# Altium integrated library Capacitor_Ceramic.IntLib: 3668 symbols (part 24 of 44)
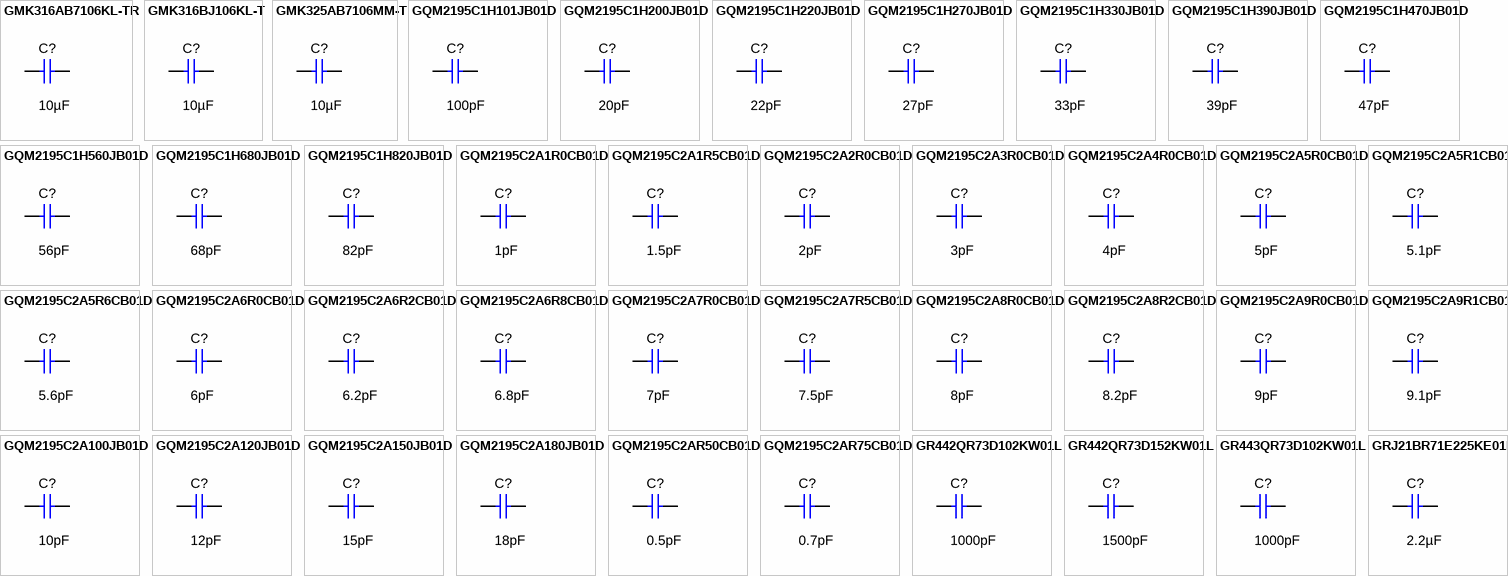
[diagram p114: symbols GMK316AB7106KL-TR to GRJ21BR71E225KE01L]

## GQM2195C2A5R1CB01D
designator C?  ValueDisplayed: 5.1pF  (hidden comment: GQM2195C2A5R1CB01D)
CAP, CERM, 5.1 pF, 100 V,+/- 5%, C0G/NP0, 0805; Manufacturer: MuRata; Polarized: N; CompType: Capacitor; Value: 5.1pF; U/M: EA; Cap_F: 0.0000000000051; Tolerance_%: 5; VDC_V: 100; Value2: 100V; TaMin_C: -55; TaMax_C: 125; Cap_Case: 0805; SizeArea_mm2: 2.5; SizeAreaWB_mm2: 6.75; SizeX_mm: 2; SizeY_mm: 1.25; SizeZ_mm: 1.45; AEC Category: Q200
signal-integrity model Cap
simulation model Cap
footprint 0805_HV
footprint 0805_HV1
footprint 0805
footprint 0805M
footprint 0805L
pins: 1, 2

## GQM2195C2A5R6CB01D
designator C?  ValueDisplayed: 5.6pF  (hidden comment: GQM2195C2A5R6CB01D)
CAP, CERM, 5.6 pF, 100 V,+/- 5%, C0G/NP0, 0805; Manufacturer: MuRata; Polarized: N; CompType: Capacitor; Value: 5.6pF; U/M: EA; Cap_F: 0.0000000000056; Tolerance_%: 5; VDC_V: 100; Value2: 100V; TaMin_C: -55; TaMax_C: 125; Cap_Case: 0805; SizeArea_mm2: 2.5; SizeAreaWB_mm2: 6.75; SizeX_mm: 2; SizeY_mm: 1.25; SizeZ_mm: 1.45; AEC Category: Q200
signal-integrity model Cap
simulation model Cap
footprint 0805_HV
footprint 0805_HV1
footprint 0805
footprint 0805M
footprint 0805L
pins: 1, 2

## GQM2195C2A6R0CB01D
designator C?  ValueDisplayed: 6pF  (hidden comment: GQM2195C2A6R0CB01D)
CAP, CERM, 6 pF, 100 V,+/- 5%, C0G/NP0, 0805; Manufacturer: MuRata; Polarized: N; CompType: Capacitor; Value: 6pF; U/M: EA; Cap_F: 0.000000000006; Tolerance_%: 5; VDC_V: 100; Value2: 100V; TaMin_C: -55; TaMax_C: 125; Cap_Case: 0805; SizeArea_mm2: 2.5; SizeAreaWB_mm2: 6.75; SizeX_mm: 2; SizeY_mm: 1.25; SizeZ_mm: 1.45; AEC Category: Q200
signal-integrity model Cap
simulation model Cap
footprint 0805_HV
footprint 0805_HV1
footprint 0805
footprint 0805M
footprint 0805L
pins: 1, 2

## GQM2195C2A6R2CB01D
designator C?  ValueDisplayed: 6.2pF  (hidden comment: GQM2195C2A6R2CB01D)
CAP, CERM, 6.2 pF, 100 V,+/- 5%, C0G/NP0, 0805; Manufacturer: MuRata; Polarized: N; CompType: Capacitor; Value: 6.2pF; U/M: EA; Cap_F: 0.0000000000062; Tolerance_%: 5; VDC_V: 100; Value2: 100V; TaMin_C: -55; TaMax_C: 125; Cap_Case: 0805; SizeArea_mm2: 2.5; SizeAreaWB_mm2: 6.75; SizeX_mm: 2; SizeY_mm: 1.25; SizeZ_mm: 1.45; AEC Category: Q200
signal-integrity model Cap
simulation model Cap
footprint 0805_HV
footprint 0805_HV1
footprint 0805
footprint 0805M
footprint 0805L
pins: 1, 2

## GQM2195C2A6R8CB01D
designator C?  ValueDisplayed: 6.8pF  (hidden comment: GQM2195C2A6R8CB01D)
CAP, CERM, 6.8 pF, 100 V,+/- 5%, C0G/NP0, 0805; Manufacturer: MuRata; Polarized: N; CompType: Capacitor; Value: 6.8pF; U/M: EA; Cap_F: 0.0000000000068; Tolerance_%: 5; VDC_V: 100; Value2: 100V; TaMin_C: -55; TaMax_C: 125; Cap_Case: 0805; SizeArea_mm2: 2.5; SizeAreaWB_mm2: 6.75; SizeX_mm: 2; SizeY_mm: 1.25; SizeZ_mm: 1.45; AEC Category: Q200
signal-integrity model Cap
simulation model Cap
footprint 0805_HV
footprint 0805_HV1
footprint 0805
footprint 0805M
footprint 0805L
pins: 1, 2

## GQM2195C2A7R0CB01D
designator C?  ValueDisplayed: 7pF  (hidden comment: GQM2195C2A7R0CB01D)
CAP, CERM, 7 pF, 100 V,+/- 5%, C0G/NP0, 0805; Manufacturer: MuRata; Polarized: N; CompType: Capacitor; Value: 7pF; U/M: EA; Cap_F: 0.000000000007; Tolerance_%: 5; VDC_V: 100; Value2: 100V; TaMin_C: -55; TaMax_C: 125; Cap_Case: 0805; SizeArea_mm2: 2.5; SizeAreaWB_mm2: 6.75; SizeX_mm: 2; SizeY_mm: 1.25; SizeZ_mm: 1.45; AEC Category: Q200
signal-integrity model Cap
simulation model Cap
footprint 0805_HV
footprint 0805_HV1
footprint 0805
footprint 0805M
footprint 0805L
pins: 1, 2

## GQM2195C2A7R5CB01D
designator C?  ValueDisplayed: 7.5pF  (hidden comment: GQM2195C2A7R5CB01D)
CAP, CERM, 7.5 pF, 100 V,+/- 5%, C0G/NP0, 0805; Manufacturer: MuRata; Polarized: N; CompType: Capacitor; Value: 7.5pF; U/M: EA; Cap_F: 0.0000000000075; Tolerance_%: 5; VDC_V: 100; Value2: 100V; TaMin_C: -55; TaMax_C: 125; Cap_Case: 0805; SizeArea_mm2: 2.5; SizeAreaWB_mm2: 6.75; SizeX_mm: 2; SizeY_mm: 1.25; SizeZ_mm: 1.45; AEC Category: Q200
signal-integrity model Cap
simulation model Cap
footprint 0805_HV
footprint 0805_HV1
footprint 0805
footprint 0805M
footprint 0805L
pins: 1, 2

## GQM2195C2A8R0CB01D
designator C?  ValueDisplayed: 8pF  (hidden comment: GQM2195C2A8R0CB01D)
CAP, CERM, 8 pF, 100 V,+/- 5%, C0G/NP0, 0805; Manufacturer: MuRata; Polarized: N; CompType: Capacitor; Value: 8pF; U/M: EA; Cap_F: 0.000000000008; Tolerance_%: 5; VDC_V: 100; Value2: 100V; TaMin_C: -55; TaMax_C: 125; Cap_Case: 0805; SizeArea_mm2: 2.5; SizeAreaWB_mm2: 6.75; SizeX_mm: 2; SizeY_mm: 1.25; SizeZ_mm: 1.45; AEC Category: Q200
signal-integrity model Cap
simulation model Cap
footprint 0805_HV
footprint 0805_HV1
footprint 0805
footprint 0805M
footprint 0805L
pins: 1, 2

## GQM2195C2A8R2CB01D
designator C?  ValueDisplayed: 8.2pF  (hidden comment: GQM2195C2A8R2CB01D)
CAP, CERM, 8.2 pF, 100 V,+/- 5%, C0G/NP0, 0805; Manufacturer: MuRata; Polarized: N; CompType: Capacitor; Value: 8.2pF; U/M: EA; Cap_F: 0.0000000000082; Tolerance_%: 5; VDC_V: 100; Value2: 100V; TaMin_C: -55; TaMax_C: 125; Cap_Case: 0805; SizeArea_mm2: 2.5; SizeAreaWB_mm2: 6.75; SizeX_mm: 2; SizeY_mm: 1.25; SizeZ_mm: 1.45; AEC Category: Q200
signal-integrity model Cap
simulation model Cap
footprint 0805_HV
footprint 0805_HV1
footprint 0805
footprint 0805M
footprint 0805L
pins: 1, 2

## GQM2195C2A9R0CB01D
designator C?  ValueDisplayed: 9pF  (hidden comment: GQM2195C2A9R0CB01D)
CAP, CERM, 9 pF, 100 V,+/- 5%, C0G/NP0, 0805; Manufacturer: MuRata; Polarized: N; CompType: Capacitor; Value: 9pF; U/M: EA; Cap_F: 0.000000000009; Tolerance_%: 5; VDC_V: 100; Value2: 100V; TaMin_C: -55; TaMax_C: 125; Cap_Case: 0805; SizeArea_mm2: 2.5; SizeAreaWB_mm2: 6.75; SizeX_mm: 2; SizeY_mm: 1.25; SizeZ_mm: 1.45; AEC Category: Q200
signal-integrity model Cap
simulation model Cap
footprint 0805_HV
footprint 0805_HV1
footprint 0805
footprint 0805M
footprint 0805L
pins: 1, 2

## GQM2195C2A9R1CB01D
designator C?  ValueDisplayed: 9.1pF  (hidden comment: GQM2195C2A9R1CB01D)
CAP, CERM, 9.1 pF, 100 V,+/- 5%, C0G/NP0, 0805; Manufacturer: MuRata; Polarized: N; CompType: Capacitor; Value: 9.1pF; U/M: EA; Cap_F: 0.0000000000091; Tolerance_%: 5; VDC_V: 100; Value2: 100V; TaMin_C: -55; TaMax_C: 125; Cap_Case: 0805; SizeArea_mm2: 2.5; SizeAreaWB_mm2: 6.75; SizeX_mm: 2; SizeY_mm: 1.25; SizeZ_mm: 1.45; AEC Category: Q200
signal-integrity model Cap
simulation model Cap
footprint 0805_HV
footprint 0805_HV1
footprint 0805
footprint 0805M
footprint 0805L
pins: 1, 2

## GQM2195C2A100JB01D
designator C?  ValueDisplayed: 10pF  (hidden comment: GQM2195C2A100JB01D)
CAP, CERM, 10 pF, 100 V,+/- 5%, C0G/NP0, 0805; Manufacturer: MuRata; Polarized: N; CompType: Capacitor; Value: 10pF; U/M: EA; Cap_F: 0.00000000001; Tolerance_%: 5; VDC_V: 100; Value2: 100V; TaMin_C: -55; TaMax_C: 125; Cap_Case: 0805; SizeArea_mm2: 2.5; SizeAreaWB_mm2: 6.75; SizeX_mm: 2; SizeY_mm: 1.25; SizeZ_mm: 1.45; AEC Category: Q200
signal-integrity model Cap
simulation model Cap
footprint 0805_HV
footprint 0805_HV1
footprint 0805
footprint 0805M
footprint 0805L
pins: 1, 2

## GQM2195C2A120JB01D
designator C?  ValueDisplayed: 12pF  (hidden comment: GQM2195C2A120JB01D)
CAP, CERM, 12 pF, 100 V,+/- 5%, C0G/NP0, 0805; Manufacturer: MuRata; Polarized: N; CompType: Capacitor; Value: 12pF; U/M: EA; Cap_F: 0.000000000012; Tolerance_%: 5; VDC_V: 100; Value2: 100V; TaMin_C: -55; TaMax_C: 125; Cap_Case: 0805; SizeArea_mm2: 2.5; SizeAreaWB_mm2: 6.75; SizeX_mm: 2; SizeY_mm: 1.25; SizeZ_mm: 1.45; AEC Category: Q200
signal-integrity model Cap
simulation model Cap
footprint 0805_HV
footprint 0805_HV1
footprint 0805
footprint 0805M
footprint 0805L
pins: 1, 2

## GQM2195C2A150JB01D
designator C?  ValueDisplayed: 15pF  (hidden comment: GQM2195C2A150JB01D)
CAP, CERM, 15 pF, 100 V,+/- 5%, C0G/NP0, 0805; Manufacturer: MuRata; Polarized: N; CompType: Capacitor; Value: 15pF; U/M: EA; Cap_F: 0.000000000015; Tolerance_%: 5; VDC_V: 100; Value2: 100V; TaMin_C: -55; TaMax_C: 125; Cap_Case: 0805; SizeArea_mm2: 2.5; SizeAreaWB_mm2: 6.75; SizeX_mm: 2; SizeY_mm: 1.25; SizeZ_mm: 1.45; AEC Category: Q200
signal-integrity model Cap
simulation model Cap
footprint 0805_HV
footprint 0805_HV1
footprint 0805
footprint 0805M
footprint 0805L
pins: 1, 2

## GQM2195C2A180JB01D
designator C?  ValueDisplayed: 18pF  (hidden comment: GQM2195C2A180JB01D)
CAP, CERM, 18 pF, 100 V,+/- 5%, C0G/NP0, 0805; Manufacturer: MuRata; Polarized: N; CompType: Capacitor; Value: 18pF; U/M: EA; Cap_F: 0.000000000018; Tolerance_%: 5; VDC_V: 100; Value2: 100V; TaMin_C: -55; TaMax_C: 125; Cap_Case: 0805; SizeArea_mm2: 2.5; SizeAreaWB_mm2: 6.75; SizeX_mm: 2; SizeY_mm: 1.25; SizeZ_mm: 1.45; AEC Category: Q200
signal-integrity model Cap
simulation model Cap
footprint 0805_HV
footprint 0805_HV1
footprint 0805
footprint 0805M
footprint 0805L
pins: 1, 2

## GQM2195C2AR50CB01D
designator C?  ValueDisplayed: 0.5pF  (hidden comment: GQM2195C2AR50CB01D)
CAP, CERM, 0.5 pF, 100 V,+/- 5%, C0G/NP0, 0805; Manufacturer: MuRata; Polarized: N; CompType: Capacitor; Value: 0.5pF; U/M: EA; Cap_F: 0.0000000000005; Tolerance_%: 5; VDC_V: 100; Value2: 100V; TaMin_C: -55; TaMax_C: 125; Cap_Case: 0805; SizeArea_mm2: 2.5; SizeAreaWB_mm2: 6.75; SizeX_mm: 2; SizeY_mm: 1.25; SizeZ_mm: 1.45; AEC Category: Q200
signal-integrity model Cap
simulation model Cap
footprint 0805_HV
footprint 0805_HV1
footprint 0805
footprint 0805M
footprint 0805L
pins: 1, 2

## GQM2195C2AR75CB01D
designator C?  ValueDisplayed: 0.7pF  (hidden comment: GQM2195C2AR75CB01D)
CAP, CERM, 0.7 pF, 100 V,+/- 5%, C0G/NP0, 0805; Manufacturer: MuRata; Polarized: N; CompType: Capacitor; Value: 0.7pF; U/M: EA; Cap_F: 0.0000000000007; Tolerance_%: 5; VDC_V: 100; Value2: 100V; TaMin_C: -55; TaMax_C: 125; Cap_Case: 0805; SizeArea_mm2: 2.5; SizeAreaWB_mm2: 6.75; SizeX_mm: 2; SizeY_mm: 1.25; SizeZ_mm: 1.45; AEC Category: Q200
signal-integrity model Cap
simulation model Cap
footprint 0805_HV
footprint 0805_HV1
footprint 0805
footprint 0805M
footprint 0805L
pins: 1, 2

## GR442QR73D102KW01L
designator C?  ValueDisplayed: 1000pF  (hidden comment: GR442QR73D102KW01L)
CAP, CERM, 1000 pF, 2000 V,+/- 10%, X7R, 1808; Manufacturer: MuRata; Polarized: N; CompType: Capacitor; Value: 1000pF; U/M: EA; Cap_F: 0.000000001; Tolerance_%: 10; VDC_V: 2000; Value2: 2000V; TaMin_C: -55; TaMax_C: 125; Cap_Case: 1808; SizeArea_mm2: 9; SizeAreaWB_mm2: 16.5; SizeX_mm: 4.5; SizeY_mm: 2; SizeZ_mm: 2.03; AEC Category: Q200
signal-integrity model Cap
simulation model Cap
footprint 1808
footprint 1808_M
footprint 1808_L
pins: 1, 2

## GR442QR73D152KW01L
designator C?  ValueDisplayed: 1500pF  (hidden comment: GR442QR73D152KW01L)
CAP, CERM, 1500 pF, 2000 V,+/- 10%, X7R, 1808; Manufacturer: MuRata; Polarized: N; CompType: Capacitor; Value: 1500pF; U/M: EA; Cap_F: 0.0000000015; Tolerance_%: 10; VDC_V: 2000; Value2: 2000V; TaMin_C: -55; TaMax_C: 125; Cap_Case: 1808; SizeArea_mm2: 9; SizeAreaWB_mm2: 16.5; SizeX_mm: 4.5; SizeY_mm: 2; SizeZ_mm: 2.03; AEC Category: Q200; Green_Lifecycle: Not Set; Green_REACh: Incomplete
signal-integrity model Cap
simulation model Cap
footprint 1808
footprint 1808_M
footprint 1808_L
pins: 1, 2

## GR443QR73D102KW01L
designator C?  ValueDisplayed: 1000pF  (hidden comment: GR443QR73D102KW01L)
CAP, CERM, 1000 pF, 2000 V,+/- 10%, X7R, 1812; Manufacturer: MuRata; Polarized: N; CompType: Capacitor; Value: 1000pF; U/M: EA; Cap_F: 0.000000001; Tolerance_%: 10; VDC_V: 2000; Value2: 2000V; TaMin_C: -55; TaMax_C: 125; Cap_Case: 1812; SizeArea_mm2: 14.4; SizeAreaWB_mm2: 23.1; SizeX_mm: 4.5; SizeY_mm: 3.2; SizeZ_mm: 1.35; AEC Category: Q200
signal-integrity model Cap
simulation model Cap
footprint 1812
footprint 1812M
footprint 1812L
footprint 1812_HV
pins: 1, 2

## GRJ21BR71E225KE01L
designator C?  ValueDisplayed: 2.2µF  (hidden comment: GRJ21BR71E225KE01L)
CAP, CERM, 2.2 µF, 25 V,+/- 10%, X7R, 0805; Manufacturer: MuRata; Polarized: N; CompType: Capacitor; Value: 2.2uF; U/M: EA; Cap_F: 0.0000022; Tolerance_%: 10; VDC_V: 25; Value2: 25V; TaMin_C: -55; TaMax_C: 125; Cap_Case: 0805; SizeArea_mm2: 2.5; SizeAreaWB_mm2: 6.75; SizeX_mm: 2; SizeY_mm: 1.25; SizeZ_mm: 1.45; AEC Category: Q200
signal-integrity model Cap
simulation model Cap
footprint 0805_HV
footprint 0805_HV1
footprint 0805
footprint 0805M
footprint 0805L
pins: 1, 2

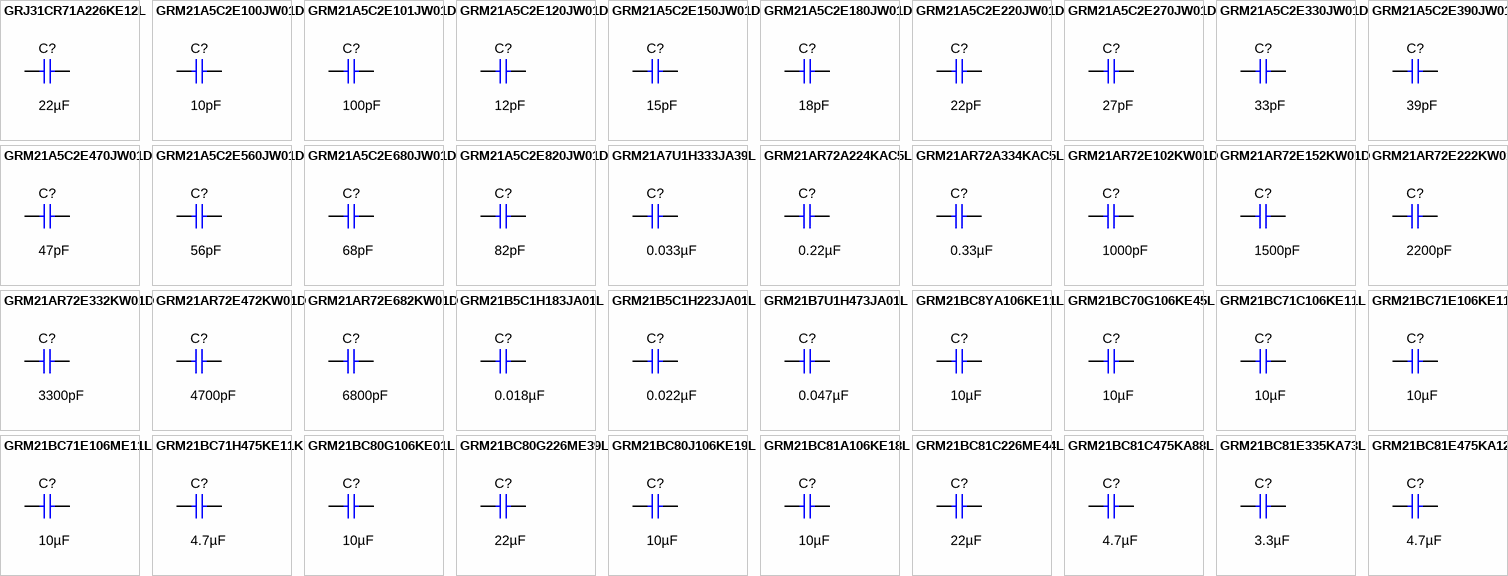
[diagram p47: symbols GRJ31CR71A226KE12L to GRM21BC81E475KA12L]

## GRJ31CR71A226KE12L
designator C?  ValueDisplayed: 22µF  (hidden comment: GRJ31CR71A226KE12L)
CAP, CERM, 22 µF, 10 V,+/- 10%, X7R, 1206; Manufacturer: MuRata; Polarized: N; CompType: Capacitor; Value: 22uF; U/M: EA; Cap_F: 0.000022; Tolerance_%: 10; Value2: 10V; TaMin_C: -55; TaMax_C: 125; Cap_Case: 1206; SizeArea_mm2: 5.12; SizeAreaWB_mm2: 10.92; SizeX_mm: 3.2; SizeY_mm: 1.6; SizeZ_mm: 1.9; AEC Category: Q200
signal-integrity model Cap
simulation model Cap
footprint 1206_190
footprint 1206_190M
footprint 1206_190L
pins: 1, 2

## GRM21A5C2E100JW01D
designator C?  ValueDisplayed: 10pF  (hidden comment: GRM21A5C2E100JW01D)
CAP, CERM, 10 pF, 250 V,+/- 5%, C0G/NP0, 0805; Manufacturer: MuRata; Polarized: N; CompType: Capacitor; Value: 10pF; U/M: EA; Cap_F: 0.00000000001; Tolerance_%: 5; VDC_V: 250; Value2: 250V; TaMin_C: -55; TaMax_C: 125; Cap_Case: 0805; SizeArea_mm2: 2.5; SizeAreaWB_mm2: 6.75; SizeX_mm: 2; SizeY_mm: 1.25; SizeZ_mm: 1.45; AEC Category: Q200
signal-integrity model Cap
simulation model Cap
footprint 0805_HV
footprint 0805_HV1
footprint 0805
footprint 0805M
footprint 0805L
pins: 1, 2

## GRM21A5C2E101JW01D
designator C?  ValueDisplayed: 100pF  (hidden comment: GRM21A5C2E101JW01D)
CAP, CERM, 100 pF, 250 V,+/- 5%, C0G/NP0, 0805; Manufacturer: MuRata; Polarized: N; CompType: Capacitor; Value: 100pF; U/M: EA; Cap_F: 0.0000000001; Tolerance_%: 5; VDC_V: 250; Value2: 250V; TaMin_C: -55; TaMax_C: 125; Cap_Case: 0805; SizeArea_mm2: 2.5; SizeAreaWB_mm2: 6.75; SizeX_mm: 2; SizeY_mm: 1.25; SizeZ_mm: 1.45; AEC Category: Q200
signal-integrity model Cap
simulation model Cap
footprint 0805_HV
footprint 0805_HV1
footprint 0805
footprint 0805M
footprint 0805L
pins: 1, 2

## GRM21A5C2E120JW01D
designator C?  ValueDisplayed: 12pF  (hidden comment: GRM21A5C2E120JW01D)
CAP, CERM, 12 pF, 250 V,+/- 5%, C0G/NP0, 0805; Manufacturer: MuRata; Polarized: N; CompType: Capacitor; Value: 12pF; U/M: EA; Cap_F: 0.000000000012; Tolerance_%: 5; VDC_V: 250; Value2: 250V; TaMin_C: -55; TaMax_C: 125; Cap_Case: 0805; SizeArea_mm2: 2.5; SizeAreaWB_mm2: 6.75; SizeX_mm: 2; SizeY_mm: 1.25; SizeZ_mm: 1.45; AEC Category: Q200
signal-integrity model Cap
simulation model Cap
footprint 0805_HV
footprint 0805_HV1
footprint 0805
footprint 0805M
footprint 0805L
pins: 1, 2

## GRM21A5C2E150JW01D
designator C?  ValueDisplayed: 15pF  (hidden comment: GRM21A5C2E150JW01D)
CAP, CERM, 15 pF, 250 V,+/- 5%, C0G/NP0, 0805; Manufacturer: MuRata; Polarized: N; CompType: Capacitor; Value: 15pF; U/M: EA; Cap_F: 0.000000000015; Tolerance_%: 5; VDC_V: 250; Value2: 250V; TaMin_C: -55; TaMax_C: 125; Cap_Case: 0805; SizeArea_mm2: 2.5; SizeAreaWB_mm2: 6.75; SizeX_mm: 2; SizeY_mm: 1.25; SizeZ_mm: 1.45; AEC Category: Q200
signal-integrity model Cap
simulation model Cap
footprint 0805_HV
footprint 0805_HV1
footprint 0805
footprint 0805M
footprint 0805L
pins: 1, 2

## GRM21A5C2E180JW01D
designator C?  ValueDisplayed: 18pF  (hidden comment: GRM21A5C2E180JW01D)
CAP, CERM, 18 pF, 250 V,+/- 5%, C0G/NP0, 0805; Manufacturer: MuRata; Polarized: N; CompType: Capacitor; Value: 18pF; U/M: EA; Cap_F: 0.000000000018; Tolerance_%: 5; VDC_V: 250; Value2: 250V; TaMin_C: -55; TaMax_C: 125; Cap_Case: 0805; SizeArea_mm2: 2.5; SizeAreaWB_mm2: 6.75; SizeX_mm: 2; SizeY_mm: 1.25; SizeZ_mm: 1.45; AEC Category: Q200
signal-integrity model Cap
simulation model Cap
footprint 0805_HV
footprint 0805_HV1
footprint 0805
footprint 0805M
footprint 0805L
pins: 1, 2

## GRM21A5C2E220JW01D
designator C?  ValueDisplayed: 22pF  (hidden comment: GRM21A5C2E220JW01D)
CAP, CERM, 22 pF, 250 V,+/- 5%, C0G/NP0, 0805; Manufacturer: MuRata; Polarized: N; CompType: Capacitor; Value: 22pF; U/M: EA; Cap_F: 0.000000000022; Tolerance_%: 5; VDC_V: 250; Value2: 250V; TaMin_C: -55; TaMax_C: 125; Cap_Case: 0805; SizeArea_mm2: 2.5; SizeAreaWB_mm2: 6.75; SizeX_mm: 2; SizeY_mm: 1.25; SizeZ_mm: 1.45; AEC Category: Q200
signal-integrity model Cap
simulation model Cap
footprint 0805_HV
footprint 0805_HV1
footprint 0805
footprint 0805M
footprint 0805L
pins: 1, 2

## GRM21A5C2E270JW01D
designator C?  ValueDisplayed: 27pF  (hidden comment: GRM21A5C2E270JW01D)
CAP, CERM, 27 pF, 250 V,+/- 5%, C0G/NP0, 0805; Manufacturer: MuRata; Polarized: N; CompType: Capacitor; Value: 27pF; U/M: EA; Cap_F: 0.000000000027; Tolerance_%: 5; VDC_V: 250; Value2: 250V; TaMin_C: -55; TaMax_C: 125; Cap_Case: 0805; SizeArea_mm2: 2.5; SizeAreaWB_mm2: 6.75; SizeX_mm: 2; SizeY_mm: 1.25; SizeZ_mm: 1.45; AEC Category: Q200
signal-integrity model Cap
simulation model Cap
footprint 0805_HV
footprint 0805_HV1
footprint 0805
footprint 0805M
footprint 0805L
pins: 1, 2

## GRM21A5C2E330JW01D
designator C?  ValueDisplayed: 33pF  (hidden comment: GRM21A5C2E330JW01D)
CAP, CERM, 33 pF, 250 V,+/- 5%, C0G/NP0, 0805; Manufacturer: MuRata; Polarized: N; CompType: Capacitor; Value: 33pF; U/M: EA; Cap_F: 0.000000000033; Tolerance_%: 5; VDC_V: 250; Value2: 250V; TaMin_C: -55; TaMax_C: 125; Cap_Case: 0805; SizeArea_mm2: 2.5; SizeAreaWB_mm2: 6.75; SizeX_mm: 2; SizeY_mm: 1.25; SizeZ_mm: 1.45; AEC Category: Q200
signal-integrity model Cap
simulation model Cap
footprint 0805_HV
footprint 0805_HV1
footprint 0805
footprint 0805M
footprint 0805L
pins: 1, 2

## GRM21A5C2E390JW01D
designator C?  ValueDisplayed: 39pF  (hidden comment: GRM21A5C2E390JW01D)
CAP, CERM, 39 pF, 250 V,+/- 5%, C0G/NP0, 0805; Manufacturer: MuRata; Polarized: N; CompType: Capacitor; Value: 39pF; U/M: EA; Cap_F: 0.000000000039; Tolerance_%: 5; VDC_V: 250; Value2: 250V; TaMin_C: -55; TaMax_C: 125; Cap_Case: 0805; SizeArea_mm2: 2.5; SizeAreaWB_mm2: 6.75; SizeX_mm: 2; SizeY_mm: 1.25; SizeZ_mm: 1.45; AEC Category: Q200
signal-integrity model Cap
simulation model Cap
footprint 0805_HV
footprint 0805_HV1
footprint 0805
footprint 0805M
footprint 0805L
pins: 1, 2

## GRM21A5C2E470JW01D
designator C?  ValueDisplayed: 47pF  (hidden comment: GRM21A5C2E470JW01D)
CAP, CERM, 47 pF, 250 V,+/- 5%, C0G/NP0, 0805; Manufacturer: MuRata; Polarized: N; CompType: Capacitor; Value: 47pF; U/M: EA; Cap_F: 0.000000000047; Tolerance_%: 5; VDC_V: 250; Value2: 250V; TaMin_C: -55; TaMax_C: 125; Cap_Case: 0805; SizeArea_mm2: 2.5; SizeAreaWB_mm2: 6.75; SizeX_mm: 2; SizeY_mm: 1.25; SizeZ_mm: 1.45; AEC Category: Q200
signal-integrity model Cap
simulation model Cap
footprint 0805_HV
footprint 0805_HV1
footprint 0805
footprint 0805M
footprint 0805L
pins: 1, 2

## GRM21A5C2E560JW01D
designator C?  ValueDisplayed: 56pF  (hidden comment: GRM21A5C2E560JW01D)
CAP, CERM, 56 pF, 250 V,+/- 5%, C0G/NP0, 0805; Manufacturer: MuRata; Polarized: N; CompType: Capacitor; Value: 56pF; U/M: EA; Cap_F: 0.000000000056; Tolerance_%: 5; VDC_V: 250; Value2: 250V; TaMin_C: -55; TaMax_C: 125; Cap_Case: 0805; SizeArea_mm2: 2.5; SizeAreaWB_mm2: 6.75; SizeX_mm: 2; SizeY_mm: 1.25; SizeZ_mm: 1.45; AEC Category: Q200
signal-integrity model Cap
simulation model Cap
footprint 0805_HV
footprint 0805_HV1
footprint 0805
footprint 0805M
footprint 0805L
pins: 1, 2

## GRM21A5C2E680JW01D
designator C?  ValueDisplayed: 68pF  (hidden comment: GRM21A5C2E680JW01D)
CAP, CERM, 68 pF, 250 V,+/- 5%, C0G/NP0, 0805; Manufacturer: MuRata; Polarized: N; CompType: Capacitor; Value: 68pF; U/M: EA; Cap_F: 0.000000000068; Tolerance_%: 5; VDC_V: 250; Value2: 250V; TaMin_C: -55; TaMax_C: 125; Cap_Case: 0805; SizeArea_mm2: 2.5; SizeAreaWB_mm2: 6.75; SizeX_mm: 2; SizeY_mm: 1.25; SizeZ_mm: 1.45; AEC Category: Q200
signal-integrity model Cap
simulation model Cap
footprint 0805_HV
footprint 0805_HV1
footprint 0805
footprint 0805M
footprint 0805L
pins: 1, 2

## GRM21A5C2E820JW01D
designator C?  ValueDisplayed: 82pF  (hidden comment: GRM21A5C2E820JW01D)
CAP, CERM, 82 pF, 250 V,+/- 5%, C0G/NP0, 0805; Manufacturer: MuRata; Polarized: N; CompType: Capacitor; Value: 82pF; U/M: EA; Cap_F: 0.000000000082; Tolerance_%: 5; VDC_V: 250; Value2: 250V; TaMin_C: -55; TaMax_C: 125; Cap_Case: 0805; SizeArea_mm2: 2.5; SizeAreaWB_mm2: 6.75; SizeX_mm: 2; SizeY_mm: 1.25; SizeZ_mm: 1.45; AEC Category: Q200
signal-integrity model Cap
simulation model Cap
footprint 0805_HV
footprint 0805_HV1
footprint 0805
footprint 0805M
footprint 0805L
pins: 1, 2

## GRM21A7U1H333JA39L
designator C?  ValueDisplayed: 0.033µF  (hidden comment: GRM21A7U1H333JA39L)
CAP, CERM, 0.033 µF, 50 V,+/- 5%, U2J, 0805; Manufacturer: MuRata; Polarized: N; CompType: Capacitor; Value: 0.033uF; U/M: EA; Cap_F: 0.000000033; Tolerance_%: 5; VDC_V: 50; Value2: 50V; TaMin_C: -55; TaMax_C: 125; Cap_Case: 0805; SizeArea_mm2: 2.5; SizeAreaWB_mm2: 6.75; SizeX_mm: 2; SizeY_mm: 1.25; SizeZ_mm: 1.45; AEC Category: Q200
signal-integrity model Cap
simulation model Cap
footprint 0805_HV
footprint 0805_HV1
footprint 0805
footprint 0805M
footprint 0805L
pins: 1, 2

## GRM21AR72A224KAC5L
designator C?  ValueDisplayed: 0.22µF  (hidden comment: GRM21AR72A224KAC5L)
CAP, CERM, 0.22 µF, 100 V,+/- 10%, X7R, 0805; Manufacturer: MuRata; Polarized: N; CompType: Capacitor; Value: 0.22uF; U/M: EA; Cap_F: 0.00000022; Tolerance_%: 10; VDC_V: 100; Value2: 100V; TaMin_C: -55; TaMax_C: 125; Cap_Case: 0805; SizeArea_mm2: 2.5; SizeAreaWB_mm2: 6.75; SizeX_mm: 2; SizeY_mm: 1.25; SizeZ_mm: 1.45; AEC Category: Q200
signal-integrity model Cap
simulation model Cap
footprint 0805_HV
footprint 0805_HV1
footprint 0805
footprint 0805M
footprint 0805L
pins: 1, 2

## GRM21AR72A334KAC5L
designator C?  ValueDisplayed: 0.33µF  (hidden comment: GRM21AR72A334KAC5L)
CAP, CERM, 0.33 µF, 100 V,+/- 10%, X7R, 0805; Manufacturer: MuRata; Polarized: N; CompType: Capacitor; Value: 0.33uF; U/M: EA; Cap_F: 0.00000033; Tolerance_%: 10; VDC_V: 100; Value2: 100V; TaMin_C: -55; TaMax_C: 125; Cap_Case: 0805; SizeArea_mm2: 2.5; SizeAreaWB_mm2: 6.75; SizeX_mm: 2; SizeY_mm: 1.25; SizeZ_mm: 1.45; AEC Category: Q200; Green_Lifecycle: Not Set; Green_REACh: Incomplete
signal-integrity model Cap
simulation model Cap
footprint 0805_HV
footprint 0805_HV1
footprint 0805
footprint 0805M
footprint 0805L
pins: 1, 2

## GRM21AR72E102KW01D
designator C?  ValueDisplayed: 1000pF  (hidden comment: GRM21AR72E102KW01D)
CAP, CERM, 1000 pF, 250 V,+/- 10%, X7R, 0805; Manufacturer: MuRata; Polarized: N; CompType: Capacitor; Value: 1000pF; U/M: EA; Cap_F: 0.000000001; Tolerance_%: 10; VDC_V: 250; Value2: 250V; TaMin_C: -55; TaMax_C: 125; Cap_Case: 0805; SizeArea_mm2: 2.5; SizeAreaWB_mm2: 6.75; SizeX_mm: 2; SizeY_mm: 1.25; SizeZ_mm: 1.45; AEC Category: Q200
signal-integrity model Cap
simulation model Cap
footprint 0805_HV
footprint 0805_HV1
footprint 0805
footprint 0805M
footprint 0805L
pins: 1, 2

## GRM21AR72E152KW01D
designator C?  ValueDisplayed: 1500pF  (hidden comment: GRM21AR72E152KW01D)
CAP, CERM, 1500 pF, 250 V,+/- 10%, X7R, 0805; Manufacturer: MuRata; Polarized: N; CompType: Capacitor; Value: 1500pF; U/M: EA; Cap_F: 0.0000000015; Tolerance_%: 10; VDC_V: 250; Value2: 250V; TaMin_C: -55; TaMax_C: 125; Cap_Case: 0805; SizeArea_mm2: 2.5; SizeAreaWB_mm2: 6.75; SizeX_mm: 2; SizeY_mm: 1.25; SizeZ_mm: 1.45; AEC Category: Q200
signal-integrity model Cap
simulation model Cap
footprint 0805_HV
footprint 0805_HV1
footprint 0805
footprint 0805M
footprint 0805L
pins: 1, 2

## GRM21AR72E222KW01D
designator C?  ValueDisplayed: 2200pF  (hidden comment: GRM21AR72E222KW01D)
CAP, CERM, 2200 pF, 250 V,+/- 10%, X7R, 0805; Manufacturer: MuRata; Polarized: N; CompType: Capacitor; Value: 2200pF; U/M: EA; Cap_F: 0.0000000022; Tolerance_%: 10; VDC_V: 250; Value2: 250V; TaMin_C: -55; TaMax_C: 125; Cap_Case: 0805; SizeArea_mm2: 2.5; SizeAreaWB_mm2: 6.75; SizeX_mm: 2; SizeY_mm: 1.25; SizeZ_mm: 1.45; AEC Category: Q200
signal-integrity model Cap
simulation model Cap
footprint 0805_HV
footprint 0805_HV1
footprint 0805
footprint 0805M
footprint 0805L
pins: 1, 2

## GRM21AR72E332KW01D
designator C?  ValueDisplayed: 3300pF  (hidden comment: GRM21AR72E332KW01D)
CAP, CERM, 3300 pF, 250 V,+/- 10%, X7R, 0805; Manufacturer: MuRata; Polarized: N; CompType: Capacitor; Value: 3300pF; U/M: EA; Cap_F: 0.0000000033; Tolerance_%: 10; VDC_V: 250; Value2: 250V; TaMin_C: -55; TaMax_C: 125; Cap_Case: 0805; SizeArea_mm2: 2.5; SizeAreaWB_mm2: 6.75; SizeX_mm: 2; SizeY_mm: 1.25; SizeZ_mm: 1.45; AEC Category: Q200
signal-integrity model Cap
simulation model Cap
footprint 0805_HV
footprint 0805_HV1
footprint 0805
footprint 0805M
footprint 0805L
pins: 1, 2

## GRM21AR72E472KW01D
designator C?  ValueDisplayed: 4700pF  (hidden comment: GRM21AR72E472KW01D)
CAP, CERM, 4700 pF, 250 V,+/- 10%, X7R, 0805; Manufacturer: MuRata; Polarized: N; CompType: Capacitor; Value: 4700pF; U/M: EA; Cap_F: 0.0000000047; Tolerance_%: 10; VDC_V: 250; Value2: 250V; TaMin_C: -55; TaMax_C: 125; Cap_Case: 0805; SizeArea_mm2: 2.5; SizeAreaWB_mm2: 6.75; SizeX_mm: 2; SizeY_mm: 1.25; SizeZ_mm: 1.45; AEC Category: Q200
signal-integrity model Cap
simulation model Cap
footprint 0805_HV
footprint 0805_HV1
footprint 0805
footprint 0805M
footprint 0805L
pins: 1, 2

## GRM21AR72E682KW01D
designator C?  ValueDisplayed: 6800pF  (hidden comment: GRM21AR72E682KW01D)
CAP, CERM, 6800 pF, 250 V,+/- 10%, X7R, 0805; Manufacturer: MuRata; Polarized: N; CompType: Capacitor; Value: 6800pF; U/M: EA; Cap_F: 0.0000000068; Tolerance_%: 10; VDC_V: 250; Value2: 250V; TaMin_C: -55; TaMax_C: 125; Cap_Case: 0805; SizeArea_mm2: 2.5; SizeAreaWB_mm2: 6.75; SizeX_mm: 2; SizeY_mm: 1.25; SizeZ_mm: 1.45; AEC Category: Q200
signal-integrity model Cap
simulation model Cap
footprint 0805_HV
footprint 0805_HV1
footprint 0805
footprint 0805M
footprint 0805L
pins: 1, 2

## GRM21B5C1H183JA01L
designator C?  ValueDisplayed: 0.018µF  (hidden comment: GRM21B5C1H183JA01L)
CAP, CERM, 0.018 µF, 50 V,+/- 5%, C0G/NP0, 0805; Manufacturer: MuRata; Polarized: N; CompType: Capacitor; Value: 0.018uF; U/M: EA; Cap_F: 0.000000018; Tolerance_%: 5; VDC_V: 50; Value2: 50V; TaMin_C: -55; TaMax_C: 125; Cap_Case: 0805; SizeArea_mm2: 2.5; SizeAreaWB_mm2: 6.75; SizeX_mm: 2; SizeY_mm: 1.25; SizeZ_mm: 1.45; AEC Category: Q200
signal-integrity model Cap
simulation model Cap
footprint 0805_HV
footprint 0805_HV1
footprint 0805
footprint 0805M
footprint 0805L
pins: 1, 2

## GRM21B5C1H223JA01L
designator C?  ValueDisplayed: 0.022µF  (hidden comment: GRM21B5C1H223JA01L)
CAP, CERM, 0.022 µF, 50 V,+/- 5%, C0G/NP0, 0805; Manufacturer: MuRata; Polarized: N; CompType: Capacitor; Value: 0.022uF; U/M: EA; Cap_F: 0.000000022; Tolerance_%: 5; VDC_V: 50; Value2: 50V; TaMin_C: -55; TaMax_C: 125; Cap_Case: 0805; SizeArea_mm2: 2.5; SizeAreaWB_mm2: 6.75; SizeX_mm: 2; SizeY_mm: 1.25; SizeZ_mm: 1.45; AEC Category: Q200; Green_Lifecycle: Active; Green_REACh: Passed
signal-integrity model Cap
simulation model Cap
footprint 0805_HV
footprint 0805_HV1
footprint 0805
footprint 0805M
footprint 0805L
pins: 1, 2

## GRM21B7U1H473JA01L
designator C?  ValueDisplayed: 0.047µF  (hidden comment: GRM21B7U1H473JA01L)
CAP, CERM, 0.047 µF, 50 V,+/- 5%, U2J, 0805; Manufacturer: MuRata; Polarized: N; CompType: Capacitor; Value: 0.047uF; U/M: EA; Cap_F: 0.000000047; Tolerance_%: 5; VDC_V: 50; Value2: 50V; TaMin_C: -55; TaMax_C: 125; Cap_Case: 0805; SizeArea_mm2: 2.5; SizeAreaWB_mm2: 6.75; SizeX_mm: 2; SizeY_mm: 1.25; SizeZ_mm: 1.45; AEC Category: Q200
signal-integrity model Cap
simulation model Cap
footprint 0805_HV
footprint 0805_HV1
footprint 0805
footprint 0805M
footprint 0805L
pins: 1, 2

## GRM21BC8YA106KE11L
designator C?  ValueDisplayed: 10µF  (hidden comment: GRM21BC8YA106KE11L)
CAP, CERM, 10 µF, 35 V,+/- 10%, X6S, 0805; Manufacturer: MuRata; Polarized: N; CompType: Capacitor; Value: 10uF; U/M: EA; Cap_F: 0.00001; Tolerance_%: 10; VDC_V: 35; Value2: 35V; TaMin_C: -55; TaMax_C: 105; Cap_Case: 0805; SizeArea_mm2: 2.5; SizeAreaWB_mm2: 6.75; SizeX_mm: 2; SizeY_mm: 1.25; SizeZ_mm: 1.45; AEC Category: Q200
signal-integrity model Cap
simulation model Cap
footprint 0805_HV
footprint 0805_HV1
footprint 0805
footprint 0805M
footprint 0805L
pins: 1, 2

## GRM21BC70G106KE45L
designator C?  ValueDisplayed: 10µF  (hidden comment: GRM21BC70G106KE45L)
CAP, CERM, 10 µF, 4 V,+/- 10%, X7S, 0805; Manufacturer: MuRata; Polarized: N; CompType: Capacitor; Value: 10uF; U/M: EA; Cap_F: 0.00001; Tolerance_%: 10; VDC_V: 4; Value2: 4V; TaMin_C: -55; TaMax_C: 125; Cap_Case: 0805; SizeArea_mm2: 2.5; SizeAreaWB_mm2: 6.75; SizeX_mm: 2; SizeY_mm: 1.25; SizeZ_mm: 1.45; AEC Category: Q200
signal-integrity model Cap
simulation model Cap
footprint 0805_HV
footprint 0805_HV1
footprint 0805
footprint 0805M
footprint 0805L
pins: 1, 2

## GRM21BC71C106KE11L
designator C?  ValueDisplayed: 10µF  (hidden comment: GRM21BC71C106KE11L)
CAP, CERM, 10 µF, 16 V,+/- 10%, X7S, 0805; Manufacturer: MuRata; Polarized: N; CompType: Capacitor; Value: 10uF; U/M: EA; Cap_F: 0.00001; Tolerance_%: 10; VDC_V: 16; Value2: 16V; TaMin_C: -55; TaMax_C: 125; Cap_Case: 0805; SizeArea_mm2: 2.5; SizeAreaWB_mm2: 6.75; SizeX_mm: 2; SizeY_mm: 1.25; SizeZ_mm: 1.45; AEC Category: Q200
signal-integrity model Cap
simulation model Cap
footprint 0805_HV
footprint 0805_HV1
footprint 0805
footprint 0805M
footprint 0805L
pins: 1, 2

## GRM21BC71E106KE11L
designator C?  ValueDisplayed: 10µF  (hidden comment: GRM21BC71E106KE11L)
CAP, CERM, 10 µF, 25 V,+/- 10%, X7S, 0805; Manufacturer: MuRata; Polarized: N; CompType: Capacitor; Value: 10uF; U/M: EA; Cap_F: 0.00001; Tolerance_%: 10; VDC_V: 25; Value2: 25V; TaMin_C: -55; TaMax_C: 125; Cap_Case: 0805; SizeArea_mm2: 2.5; SizeAreaWB_mm2: 6.75; SizeX_mm: 2; SizeY_mm: 1.25; SizeZ_mm: 1.45; AEC Category: Q200
signal-integrity model Cap
simulation model Cap
footprint 0805_HV
footprint 0805_HV1
footprint 0805
footprint 0805M
footprint 0805L
pins: 1, 2

## GRM21BC71E106ME11L
designator C?  ValueDisplayed: 10µF  (hidden comment: GRM21BC71E106ME11L)
CAP, CERM, 10 µF, 25 V,+/- 20%, X7S, 0805; Manufacturer: MuRata; Polarized: N; CompType: Capacitor; Value: 10uF; U/M: EA; Cap_F: 0.00001; Tolerance_%: 20; VDC_V: 25; Value2: 25V; TaMin_C: -55; TaMax_C: 125; Cap_Case: 0805; SizeArea_mm2: 2.5; SizeAreaWB_mm2: 6.75; SizeX_mm: 2; SizeY_mm: 1.25; SizeZ_mm: 1.45; AEC Category: Q200
signal-integrity model Cap
simulation model Cap
footprint 0805_HV
footprint 0805_HV1
footprint 0805
footprint 0805M
footprint 0805L
pins: 1, 2

## GRM21BC71H475KE11K
designator C?  ValueDisplayed: 4.7µF  (hidden comment: GRM21BC71H475KE11K)
CAP, CERM, 4.7 µF, 50 V,+/- 10%, X7S, 0805; Manufacturer: MuRata; Polarized: N; CompType: Capacitor; Value: 4.7uF; U/M: EA; Cap_F: 0.0000047; Tolerance_%: 10; VDC_V: 50; Value2: 50V; TaMin_C: -55; TaMax_C: 125; Cap_Case: 0805; SizeArea_mm2: 2.5; SizeAreaWB_mm2: 6.75; SizeX_mm: 2; SizeY_mm: 1.25; SizeZ_mm: 1.45; AEC Category: Q200
signal-integrity model Cap
simulation model Cap
footprint 0805_HV
footprint 0805_HV1
footprint 0805
footprint 0805M
footprint 0805L
pins: 1, 2

## GRM21BC80G106KE01L
designator C?  ValueDisplayed: 10µF  (hidden comment: GRM21BC80G106KE01L)
CAP, CERM, 10 µF, 4 V,+/- 10%, X6S, 0805; Manufacturer: MuRata; Polarized: N; CompType: Capacitor; Value: 10uF; U/M: EA; Cap_F: 0.00001; Tolerance_%: 10; VDC_V: 4; Value2: 4V; TaMin_C: -55; TaMax_C: 105; Cap_Case: 0805; SizeArea_mm2: 2.5; SizeAreaWB_mm2: 6.75; SizeX_mm: 2; SizeY_mm: 1.25; SizeZ_mm: 1.45; AEC Category: Q200
signal-integrity model Cap
simulation model Cap
footprint 0805_HV
footprint 0805_HV1
footprint 0805
footprint 0805M
footprint 0805L
pins: 1, 2

## GRM21BC80G226ME39L
designator C?  ValueDisplayed: 22µF  (hidden comment: GRM21BC80G226ME39L)
CAP, CERM, 22 µF, 4 V,+/- 20%, X6S, 0805; Manufacturer: MuRata; Polarized: N; CompType: Capacitor; Value: 22uF; U/M: EA; Cap_F: 0.000022; Tolerance_%: 20; VDC_V: 4; Value2: 4V; TaMin_C: -55; TaMax_C: 105; Cap_Case: 0805; SizeArea_mm2: 2.5; SizeAreaWB_mm2: 6.75; SizeX_mm: 2; SizeY_mm: 1.25; SizeZ_mm: 1.45; AEC Category: Q200
signal-integrity model Cap
simulation model Cap
footprint 0805_HV
footprint 0805_HV1
footprint 0805
footprint 0805M
footprint 0805L
pins: 1, 2

## GRM21BC80J106KE19L
designator C?  ValueDisplayed: 10µF  (hidden comment: GRM21BC80J106KE19L)
CAP, CERM, 10 µF, 6.3 V,+/- 10%, X6S, 0805; Manufacturer: MuRata; Polarized: N; CompType: Capacitor; Value: 10uF; U/M: EA; Cap_F: 0.00001; Tolerance_%: 10; VDC_V: 6.3; Value2: 6.3V; TaMin_C: -55; TaMax_C: 105; Cap_Case: 0805; SizeArea_mm2: 2.5; SizeAreaWB_mm2: 6.75; SizeX_mm: 2; SizeY_mm: 1.25; SizeZ_mm: 1.45; AEC Category: Q200
signal-integrity model Cap
simulation model Cap
footprint 0805_HV
footprint 0805_HV1
footprint 0805
footprint 0805M
footprint 0805L
pins: 1, 2

## GRM21BC81A106KE18L
designator C?  ValueDisplayed: 10µF  (hidden comment: GRM21BC81A106KE18L)
CAP, CERM, 10 µF, 10 V,+/- 10%, X6S, 0805; Manufacturer: MuRata; Polarized: N; CompType: Capacitor; Value: 10uF; U/M: EA; Cap_F: 0.00001; Tolerance_%: 10; Value2: 10V; TaMin_C: -55; TaMax_C: 105; Cap_Case: 0805; SizeArea_mm2: 2.5; SizeAreaWB_mm2: 6.75; SizeX_mm: 2; SizeY_mm: 1.25; SizeZ_mm: 1.45; AEC Category: Q200
signal-integrity model Cap
simulation model Cap
footprint 0805_HV
footprint 0805_HV1
footprint 0805
footprint 0805M
footprint 0805L
pins: 1, 2

## GRM21BC81C226ME44L
designator C?  ValueDisplayed: 22µF  (hidden comment: GRM21BC81C226ME44L)
CAP, CERM, 22 µF, 16 V,+/- 20%, X6S, 0805; Manufacturer: MuRata; Polarized: N; CompType: Capacitor; Value: 22uF; U/M: EA; Cap_F: 0.000022; Tolerance_%: 20; VDC_V: 16; Value2: 16V; TaMin_C: -55; TaMax_C: 105; Cap_Case: 0805; SizeArea_mm2: 2.5; SizeAreaWB_mm2: 6.75; SizeX_mm: 2; SizeY_mm: 1.25; SizeZ_mm: 1.45; AEC Category: Q200
signal-integrity model Cap
simulation model Cap
footprint 0805_HV
footprint 0805_HV1
footprint 0805
footprint 0805M
footprint 0805L
pins: 1, 2

## GRM21BC81C475KA88L
designator C?  ValueDisplayed: 4.7µF  (hidden comment: GRM21BC81C475KA88L)
CAP, CERM, 4.7 µF, 16 V,+/- 10%, X6S, 0805; Manufacturer: MuRata; Polarized: N; CompType: Capacitor; Value: 4.7uF; U/M: EA; Cap_F: 0.0000047; Tolerance_%: 10; VDC_V: 16; Value2: 16V; TaMin_C: -55; TaMax_C: 105; Cap_Case: 0805; SizeArea_mm2: 2.5; SizeAreaWB_mm2: 6.75; SizeX_mm: 2; SizeY_mm: 1.25; SizeZ_mm: 1.45; AEC Category: Q200
signal-integrity model Cap
simulation model Cap
footprint 0805_HV
footprint 0805_HV1
footprint 0805
footprint 0805M
footprint 0805L
pins: 1, 2

## GRM21BC81E335KA73L
designator C?  ValueDisplayed: 3.3µF  (hidden comment: GRM21BC81E335KA73L)
CAP, CERM, 3.3 µF, 25 V,+/- 10%, X6S, 0805; Manufacturer: MuRata; Polarized: N; CompType: Capacitor; Value: 3.3uF; U/M: EA; Cap_F: 0.0000033; Tolerance_%: 10; VDC_V: 25; Value2: 25V; TaMin_C: -55; TaMax_C: 105; Cap_Case: 0805; SizeArea_mm2: 2.5; SizeAreaWB_mm2: 6.75; SizeX_mm: 2; SizeY_mm: 1.25; SizeZ_mm: 1.45; AEC Category: Q200
signal-integrity model Cap
simulation model Cap
footprint 0805_HV
footprint 0805_HV1
footprint 0805
footprint 0805M
footprint 0805L
pins: 1, 2

## GRM21BC81E475KA12L
designator C?  ValueDisplayed: 4.7µF  (hidden comment: GRM21BC81E475KA12L)
CAP, CERM, 4.7 µF, 25 V,+/- 10%, X6S, 0805; Manufacturer: MuRata; Polarized: N; CompType: Capacitor; Value: 4.7uF; U/M: EA; Cap_F: 0.0000047; Tolerance_%: 10; VDC_V: 25; Value2: 25V; TaMin_C: -55; TaMax_C: 105; Cap_Case: 0805; SizeArea_mm2: 2.5; SizeAreaWB_mm2: 6.75; SizeX_mm: 2; SizeY_mm: 1.25; SizeZ_mm: 1.45; AEC Category: Q200
signal-integrity model Cap
simulation model Cap
footprint 0805_HV
footprint 0805_HV1
footprint 0805
footprint 0805M
footprint 0805L
pins: 1, 2

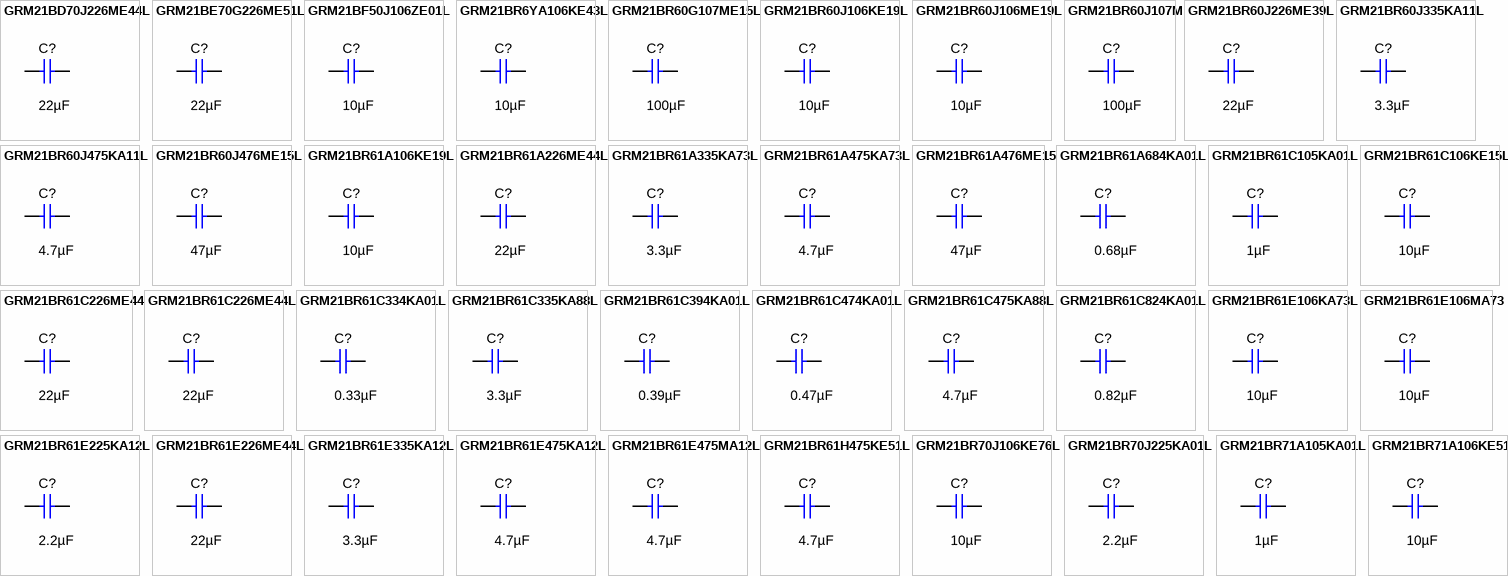
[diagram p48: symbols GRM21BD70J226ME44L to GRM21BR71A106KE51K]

## GRM21BD70J226ME44L
designator C?  ValueDisplayed: 22µF  (hidden comment: GRM21BD70J226ME44L)
CAP, CERM, 22 µF, 6.3 V,+/- 20%, X7T, 0805; Manufacturer: MuRata; Polarized: N; CompType: Capacitor; Value: 22uF; U/M: EA; Cap_F: 0.000022; Tolerance_%: 20; VDC_V: 6.3; Value2: 6.3V; TaMin_C: -55; TaMax_C: 125; Cap_Case: 0805; SizeArea_mm2: 2.5; SizeAreaWB_mm2: 6.75; SizeX_mm: 2; SizeY_mm: 1.25; SizeZ_mm: 1.45; AEC Category: Q200
signal-integrity model Cap
simulation model Cap
footprint 0805_HV
footprint 0805_HV1
footprint 0805
footprint 0805M
footprint 0805L
pins: 1, 2

## GRM21BE70G226ME51L
designator C?  ValueDisplayed: 22µF  (hidden comment: GRM21BE70G226ME51L)
CAP, CERM, 22 µF, 4 V,+/- 20%, X7U, 0805; Manufacturer: MuRata; Polarized: N; CompType: Capacitor; Value: 22uF; U/M: EA; Cap_F: 0.000022; Tolerance_%: 20; VDC_V: 4; Value2: 4V; TaMin_C: -55; TaMax_C: 125; Cap_Case: 0805; SizeArea_mm2: 2.5; SizeAreaWB_mm2: 6.75; SizeX_mm: 2; SizeY_mm: 1.25; SizeZ_mm: 1.45; AEC Category: Q200
signal-integrity model Cap
simulation model Cap
footprint 0805_HV
footprint 0805_HV1
footprint 0805
footprint 0805M
footprint 0805L
pins: 1, 2

## GRM21BF50J106ZE01L
designator C?  ValueDisplayed: 10µF  (hidden comment: GRM21BF50J106ZE01L)
CAP, CERM, 10 µF, 6.3 V,+80/-20%, Y5V, 0805; Manufacturer: MuRata; Polarized: N; CompType: Capacitor; Value: 10uF; U/M: EA; Cap_F: 0.00001; Tolerance_%: 80; ESR_ohm: 0.1; Value1: 0.1 ohm; VDC_V: 6.3; Value2: 6.3V; TaMin_C: -30; TaMax_C: 85; Cap_Case: 0805; SizeArea_mm2: 2.5; SizeAreaWB_mm2: 6.75; SizeX_mm: 2; SizeY_mm: 1.25; SizeZ_mm: 1.45; AEC Category: Q200
signal-integrity model Cap
simulation model Cap
footprint 0805_HV
footprint 0805_HV1
footprint 0805
footprint 0805M
footprint 0805L
pins: 1, 2

## GRM21BR6YA106KE43L
designator C?  ValueDisplayed: 10µF  (hidden comment: GRM21BR6YA106KE43L)
CAP, CERM, 10 µF, 35 V,+/- 10%, X5R, 0805; Manufacturer: MuRata; Polarized: N; CompType: Capacitor; Value: 10uF; U/M: EA; Cap_F: 0.00001; Tolerance_%: 10; VDC_V: 35; Value2: 35V; TaMin_C: -55; TaMax_C: 85; Cap_Case: 0805; SizeArea_mm2: 2.5; SizeAreaWB_mm2: 6.75; SizeX_mm: 2; SizeY_mm: 1.25; SizeZ_mm: 1.45; AEC Category: Q200; Green_Lifecycle: Active; Green_REACh: Passed
signal-integrity model Cap
simulation model Cap
footprint 0805_HV
footprint 0805_HV1
footprint 0805
footprint 0805M
footprint 0805L
pins: 1, 2

## GRM21BR60G107ME15L
designator C?  ValueDisplayed: 100µF  (hidden comment: GRM21BR60G107ME15L)
CAP, CERM, 100 µF, 4 V,+/- 20%, X5R, 0805; Manufacturer: MuRata; Polarized: N; CompType: Capacitor; Value: 100uF; U/M: EA; Cap_F: 0.0001; Tolerance_%: 20; VDC_V: 4; Value2: 4V; TaMin_C: -55; TaMax_C: 85; Cap_Case: 0805; SizeArea_mm2: 2.5; SizeAreaWB_mm2: 6.75; SizeX_mm: 2; SizeY_mm: 1.25; SizeZ_mm: 1.45; AEC Category: Q200
signal-integrity model Cap
simulation model Cap
footprint 0805_HV
footprint 0805_HV1
footprint 0805
footprint 0805M
footprint 0805L
pins: 1, 2

## GRM21BR60J106KE19L
designator C?  ValueDisplayed: 10µF  (hidden comment: GRM21BR60J106KE19L)
CAP, CERM, 10 µF, 6.3 V,+/- 10%, X5R, 0805; Manufacturer: MuRata; Polarized: N; CompType: Capacitor; Value: 10uF; U/M: EA; Cap_F: 0.00001; Tolerance_%: 10; ESR_ohm: 0.003; Value1: 0.003 ohm; VDC_V: 6.3; Value2: 6.3V; TaMin_C: -55; TaMax_C: 85; Cap_Case: 0805; SizeArea_mm2: 2.5; SizeAreaWB_mm2: 6.75; SizeX_mm: 2; SizeY_mm: 1.25; SizeZ_mm: 1.45; AEC Category: Q200; Green_Lifecycle: Active; Green_REACh: Passed
signal-integrity model Cap
simulation model Cap
footprint 0805_HV
footprint 0805_HV1
footprint 0805
footprint 0805M
footprint 0805L
pins: 1, 2

## GRM21BR60J106ME19L
designator C?  ValueDisplayed: 10µF  (hidden comment: GRM21BR60J106ME19L)
CAP, CERM, 10 µF, 6.3 V,+/- 20%, X5R, 0805; Manufacturer: MuRata; Polarized: N; CompType: Capacitor; Value: 10uF; U/M: EA; Cap_F: 0.00001; Tolerance_%: 20; ESR_ohm: 0.003; Value1: 0.003 ohm; VDC_V: 6.3; Value2: 6.3V; TaMin_C: -55; TaMax_C: 85; Cap_Case: 0805; SizeArea_mm2: 2.5; SizeAreaWB_mm2: 6.75; SizeX_mm: 2; SizeY_mm: 1.25; SizeZ_mm: 1.45; AEC Category: Q200; Green_Lifecycle: Active; Green_REACh: Passed
signal-integrity model Cap
simulation model Cap
footprint 0805_HV
footprint 0805_HV1
footprint 0805
footprint 0805M
footprint 0805L
pins: 1, 2

## GRM21BR60J107M
designator C?  ValueDisplayed: 100µF  (hidden comment: GRM21BR60J107M)
CAP, CERM, 100 µF, 6.3 V,+/- 20%, X5R, 0805; Manufacturer: MuRata; Polarized: N; CompType: Capacitor; Value: 100uF; U/M: EA; Cap_F: 0.0001; Tolerance_%: 20; VDC_V: 6.3; Value2: 6.3V; TaMin_C: -55; TaMax_C: 85; Cap_Case: 0805; SizeArea_mm2: 2.5; SizeAreaWB_mm2: 6.75; SizeX_mm: 2; SizeY_mm: 1.25; SizeZ_mm: 1.45; AEC Category: Q200; Green_Lifecycle: Not Set; Green_REACh: Incomplete
signal-integrity model Cap
simulation model Cap
footprint 0805_HV
footprint 0805_HV1
footprint 0805
footprint 0805M
footprint 0805L
pins: 1, 2

## GRM21BR60J226ME39L
designator C?  ValueDisplayed: 22µF  (hidden comment: GRM21BR60J226ME39L)
CAP, CERM, 22 µF, 6.3 V,+/- 20%, X5R, 0805; Manufacturer: MuRata; Polarized: N; CompType: Capacitor; Value: 22uF; U/M: EA; Cap_F: 0.000022; Tolerance_%: 20; ESR_ohm: 0.009; Value1: 0.009 ohm; VDC_V: 6.3; Value2: 6.3V; IRMS_A: 3.5; TaMin_C: -55; TaMax_C: 85; Cap_Case: 0805; SizeArea_mm2: 2.5; SizeAreaWB_mm2: 6.75; SizeX_mm: 2; SizeY_mm: 1.25; SizeZ_mm: 1.45; AEC Category: Q200; Green_Lifecycle: Active; Green_REACh: Passed
signal-integrity model Cap
simulation model Cap
footprint 0805_HV
footprint 0805_HV1
footprint 0805
footprint 0805M
footprint 0805L
pins: 1, 2

## GRM21BR60J335KA11L
designator C?  ValueDisplayed: 3.3µF  (hidden comment: GRM21BR60J335KA11L)
CAP, CERM, 3.3 µF, 6.3 V,+/- 10%, X5R, 0805; Manufacturer: MuRata; Polarized: N; CompType: Capacitor; Value: 3.3uF; U/M: EA; Cap_F: 0.0000033; Tolerance_%: 10; ESR_ohm: 0.004; Value1: 0.004 ohm; VDC_V: 6.3; Value2: 6.3V; TaMin_C: -55; TaMax_C: 85; Cap_Case: 0805; SizeArea_mm2: 2.5; SizeAreaWB_mm2: 6.75; SizeX_mm: 2; SizeY_mm: 1.25; SizeZ_mm: 1.45; AEC Category: Q200
signal-integrity model Cap
simulation model Cap
footprint 0805_HV
footprint 0805_HV1
footprint 0805
footprint 0805M
footprint 0805L
pins: 1, 2

## GRM21BR60J475KA11L
designator C?  ValueDisplayed: 4.7µF  (hidden comment: GRM21BR60J475KA11L)
CAP, CERM, 4.7 µF, 6.3 V,+/- 10%, X5R, 0805; Manufacturer: MuRata; Polarized: N; CompType: Capacitor; Value: 4.7uF; U/M: EA; Cap_F: 0.0000047; Tolerance_%: 10; VDC_V: 6.3; Value2: 6.3V; TaMin_C: -55; TaMax_C: 85; Cap_Case: 0805; SizeArea_mm2: 2.5; SizeAreaWB_mm2: 6.75; SizeX_mm: 2; SizeY_mm: 1.25; SizeZ_mm: 1.45; AEC Category: Q200
signal-integrity model Cap
simulation model Cap
footprint 0805_HV
footprint 0805_HV1
footprint 0805
footprint 0805M
footprint 0805L
pins: 1, 2

## GRM21BR60J476ME15L
designator C?  ValueDisplayed: 47µF  (hidden comment: GRM21BR60J476ME15L)
CAP, CERM, 47 µF, 6.3 V,+/- 20%, X5R, 0805; Manufacturer: MuRata; Polarized: N; CompType: Capacitor; Value: 47uF; U/M: EA; Cap_F: 0.000047; Tolerance_%: 20; VDC_V: 6.3; Value2: 6.3V; TaMin_C: -55; TaMax_C: 85; Cap_Case: 0805; SizeArea_mm2: 2.5; SizeAreaWB_mm2: 6.75; SizeX_mm: 2; SizeY_mm: 1.25; SizeZ_mm: 1.45; AEC Category: Q200; Green_Lifecycle: Active; Green_REACh: Passed
signal-integrity model Cap
simulation model Cap
footprint 0805_HV
footprint 0805_HV1
footprint 0805
footprint 0805M
footprint 0805L
pins: 1, 2

## GRM21BR61A106KE19L
designator C?  ValueDisplayed: 10µF  (hidden comment: GRM21BR61A106KE19L)
CAP, CERM, 10 µF, 10 V,+/- 10%, X5R, 0805; Manufacturer: MuRata; Polarized: N; CompType: Capacitor; Value: 10uF; U/M: EA; Cap_F: 0.00001; Tolerance_%: 10; ESR_ohm: 0.002; Value1: 0.002 ohm; Value2: 10V; TaMin_C: -55; TaMax_C: 85; Cap_Case: 0805; SizeArea_mm2: 2.5; SizeAreaWB_mm2: 6.75; SizeX_mm: 2; SizeY_mm: 1.25; SizeZ_mm: 1.45; AEC Category: Q200; Green_Lifecycle: Active; Green_REACh: Passed
signal-integrity model Cap
simulation model Cap
footprint 0805_HV
footprint 0805_HV1
footprint 0805
footprint 0805M
footprint 0805L
pins: 1, 2

## GRM21BR61A226ME44L
designator C?  ValueDisplayed: 22µF  (hidden comment: GRM21BR61A226ME44L)
CAP, CERM, 22 µF, 10 V,+/- 20%, X5R, 0805; Manufacturer: MuRata; Polarized: N; CompType: Capacitor; Value: 22uF; U/M: EA; Cap_F: 0.000022; Tolerance_%: 20; VDC_V: 10; Value2: 10V; TaMin_C: -55; TaMax_C: 85; Cap_Case: 0805; SizeArea_mm2: 2.5; SizeAreaWB_mm2: 6.75; SizeX_mm: 2; SizeY_mm: 1.25; SizeZ_mm: 1.45; AEC Category: Q200; Green_Lifecycle: Not Set; Green_REACh: Incomplete
signal-integrity model Cap
simulation model Cap
footprint 0805_HV
footprint 0805_HV1
footprint 0805
footprint 0805M
footprint 0805L
pins: 1, 2

## GRM21BR61A335KA73L
designator C?  ValueDisplayed: 3.3µF  (hidden comment: GRM21BR61A335KA73L)
CAP, CERM, 3.3 µF, 10 V,+/- 10%, X5R, 0805; Manufacturer: MuRata; Polarized: N; CompType: Capacitor; Value: 3.3uF; U/M: EA; Cap_F: 0.0000033; Tolerance_%: 10; Value2: 10V; TaMin_C: -55; TaMax_C: 85; Cap_Case: 0805; SizeArea_mm2: 2.5; SizeAreaWB_mm2: 6.75; SizeX_mm: 2; SizeY_mm: 1.25; SizeZ_mm: 1.45; AEC Category: Q200
signal-integrity model Cap
simulation model Cap
footprint 0805_HV
footprint 0805_HV1
footprint 0805
footprint 0805M
footprint 0805L
pins: 1, 2

## GRM21BR61A475KA73L
designator C?  ValueDisplayed: 4.7µF  (hidden comment: GRM21BR61A475KA73L)
CAP, CERM, 4.7 µF, 10 V,+/- 10%, X5R, 0805; Manufacturer: MuRata; Polarized: N; CompType: Capacitor; Value: 4.7uF; U/M: EA; Cap_F: 0.0000047; Tolerance_%: 10; Value2: 10V; TaMin_C: -55; TaMax_C: 85; Cap_Case: 0805; SizeArea_mm2: 2.5; SizeAreaWB_mm2: 6.75; SizeX_mm: 2; SizeY_mm: 1.25; SizeZ_mm: 1.45; AEC Category: Q200; Green_Lifecycle: Active; Green_REACh: Passed
signal-integrity model Cap
simulation model Cap
footprint 0805_HV
footprint 0805_HV1
footprint 0805
footprint 0805M
footprint 0805L
pins: 1, 2

## GRM21BR61A476ME15
designator C?  ValueDisplayed: 47µF  (hidden comment: GRM21BR61A476ME15)
CAP, CERM, 47 µF, 10 V,+/- 20%, X5R, 0805; Manufacturer: MuRata; Polarized: N; CompType: Capacitor; Value: 47uF; U/M: EA; Cap_F: 0.000047; Tolerance_%: 20; VDC_V: 10; Value2: 10V; TaMin_C: -55; TaMax_C: 85; Cap_Case: 0805; SizeArea_mm2: 2.5; SizeAreaWB_mm2: 6.75; SizeX_mm: 2; SizeY_mm: 1.25; SizeZ_mm: 1.45; AEC Category: Q200; Green_Lifecycle: Active; Green_REACh: Passed
signal-integrity model Cap
simulation model Cap
footprint 0805_HV
footprint 0805_HV1
footprint 0805
footprint 0805M
footprint 0805L
pins: 1, 2

## GRM21BR61A684KA01L
designator C?  ValueDisplayed: 0.68µF  (hidden comment: GRM21BR61A684KA01L)
CAP, CERM, 0.68 µF, 10 V,+/- 10%, X5R, 0805; Manufacturer: MuRata; Polarized: N; CompType: Capacitor; Value: 0.68uF; U/M: EA; Cap_F: 0.00000068; Tolerance_%: 10; Value2: 10V; TaMin_C: -55; TaMax_C: 85; Cap_Case: 0805; SizeArea_mm2: 2.5; SizeAreaWB_mm2: 6.75; SizeX_mm: 2; SizeY_mm: 1.25; SizeZ_mm: 1.45; AEC Category: Q200
signal-integrity model Cap
simulation model Cap
footprint 0805_HV
footprint 0805_HV1
footprint 0805
footprint 0805M
footprint 0805L
pins: 1, 2

## GRM21BR61C105KA01L
designator C?  ValueDisplayed: 1µF  (hidden comment: GRM21BR61C105KA01L)
CAP, CERM, 1 µF, 16 V,+/- 10%, X5R, 0805; Manufacturer: MuRata; Polarized: N; CompType: Capacitor; Value: 1uF; U/M: EA; Cap_F: 0.000001; Tolerance_%: 10; VDC_V: 16; Value2: 16V; TaMin_C: -55; TaMax_C: 85; Cap_Case: 0805; SizeArea_mm2: 2.5; SizeAreaWB_mm2: 6.75; SizeX_mm: 2; SizeY_mm: 1.25; SizeZ_mm: 1.45; AEC Category: Q200
signal-integrity model Cap
simulation model Cap
footprint 0805_HV
footprint 0805_HV1
footprint 0805
footprint 0805M
footprint 0805L
pins: 1, 2

## GRM21BR61C106KE15L
designator C?  ValueDisplayed: 10µF  (hidden comment: GRM21BR61C106KE15L)
CAP, CERM, 10 µF, 16 V,+/- 10%, X5R, 0805; Manufacturer: MuRata; Polarized: N; CompType: Capacitor; Value: 10uF; U/M: EA; Cap_F: 0.00001; Tolerance_%: 10; ESR_ohm: 0.008; Value1: 0.008 ohm; VDC_V: 16; Value2: 16V; TaMin_C: -55; TaMax_C: 85; Cap_Case: 0805; SizeArea_mm2: 2.5; SizeAreaWB_mm2: 6.75; SizeX_mm: 2; SizeY_mm: 1.25; SizeZ_mm: 1.45; AEC Category: Q200; Green_Lifecycle: Active; Green_REACh: Passed
signal-integrity model Cap
simulation model Cap
footprint 0805_HV
footprint 0805_HV1
footprint 0805
footprint 0805M
footprint 0805L
pins: 1, 2

## GRM21BR61C226ME44
designator C?  ValueDisplayed: 22µF  (hidden comment: GRM21BR61C226ME44)
CAP, CERM, 22 µF, 16 V,+/- 20%, X5R, 0805; Manufacturer: MuRata; Polarized: N; CompType: Capacitor; Value: 22uF; U/M: EA; Cap_F: 0.000022; Tolerance_%: 20; VDC_V: 16; Value2: 16V; TaMin_C: -55; TaMax_C: 85; Cap_Case: 0805; SizeArea_mm2: 2.5; SizeAreaWB_mm2: 6.75; SizeX_mm: 2; SizeY_mm: 1.25; SizeZ_mm: 1.45; AEC Category: Q200; Green_Lifecycle: Active; Green_REACh: Passed
signal-integrity model Cap
simulation model Cap
footprint 0805_HV
footprint 0805_HV1
footprint 0805
footprint 0805M
footprint 0805L
pins: 1, 2

## GRM21BR61C226ME44L
designator C?  ValueDisplayed: 22µF  (hidden comment: GRM21BR61C226ME44L)
CAP, CERM, 22 µF, 16 V,+/- 20%, X5R, 0805; Manufacturer: MuRata; Polarized: N; CompType: Capacitor; Value: 22uF; U/M: EA; Cap_F: 0.000022; Tolerance_%: 20; VDC_V: 16; Value2: 16V; TaMin_C: -55; TaMax_C: 85; Cap_Case: 0805; SizeArea_mm2: 2.5; SizeAreaWB_mm2: 6.75; SizeX_mm: 2; SizeY_mm: 1.25; SizeZ_mm: 1.45; AEC Category: Q200
signal-integrity model Cap
simulation model Cap
footprint 0805_HV
footprint 0805_HV1
footprint 0805
footprint 0805M
footprint 0805L
pins: 1, 2

## GRM21BR61C334KA01L
designator C?  ValueDisplayed: 0.33µF  (hidden comment: GRM21BR61C334KA01L)
CAP, CERM, 0.33 µF, 16 V,+/- 10%, X5R, 0805; Manufacturer: MuRata; Polarized: N; CompType: Capacitor; Value: 0.33uF; U/M: EA; Cap_F: 0.00000033; Tolerance_%: 10; VDC_V: 16; Value2: 16V; TaMin_C: -55; TaMax_C: 85; Cap_Case: 0805; SizeArea_mm2: 2.5; SizeAreaWB_mm2: 6.75; SizeX_mm: 2; SizeY_mm: 1.25; SizeZ_mm: 1.45; AEC Category: Q200
signal-integrity model Cap
simulation model Cap
footprint 0805_HV
footprint 0805_HV1
footprint 0805
footprint 0805M
footprint 0805L
pins: 1, 2

## GRM21BR61C335KA88L
designator C?  ValueDisplayed: 3.3µF  (hidden comment: GRM21BR61C335KA88L)
CAP, CERM, 3.3 µF, 16 V,+/- 10%, X5R, 0805; Manufacturer: MuRata; Polarized: N; CompType: Capacitor; Value: 3.3uF; U/M: EA; Cap_F: 0.0000033; Tolerance_%: 10; ESR_ohm: 0.007; Value1: 0.007 ohm; VDC_V: 16; Value2: 16V; TaMin_C: -55; TaMax_C: 85; Cap_Case: 0805; SizeArea_mm2: 2.5; SizeAreaWB_mm2: 6.75; SizeX_mm: 2; SizeY_mm: 1.25; SizeZ_mm: 1.45; AEC Category: Q200
signal-integrity model Cap
simulation model Cap
footprint 0805_HV
footprint 0805_HV1
footprint 0805
footprint 0805M
footprint 0805L
pins: 1, 2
